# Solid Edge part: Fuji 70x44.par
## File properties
Title: Lines 70x44
Author: DESYS
Template: Parte SCARABEO.par
Last saved by: i.fialdini
Revision: 30
Application: Solid Edge
Tipo di contenuto documento: 0
Precisione: 0.990
Document Number: 6002
Revision: 0
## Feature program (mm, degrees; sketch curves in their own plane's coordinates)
sketch for "unnamed Protrusion 1" plane through (0, 0, 0) normal (0, -1, 0) x-axis (1, 0, 0)
  line (-245, 195) -> (-250, 190)
  line (-145, 195) -> (-245, 195)
  line (-145, 195) -> (-140, 190)
  dimension (linear) = 145
extrude "unnamed Protrusion 1" add finite 140 along -normal
fillet "Rotondo_22" radius 35
lofted cutout "unnamed LoftedCutout 1"
fillet "Rotondo_46" radius 90
sketch for "unnamed Cutout 1" plane through (0, 0, 0) normal (0, -1, 0) x-axis (-1, 0, 0)
  line (-265, -190) -> (265, -190)
  arc centre (265, -155) radius 35 from (300, -155) to (265, -190) cw
  line (300, -155) -> (300, 125)
  arc centre (265, 125) radius 35 from (265, 160) to (300, 125) cw
  line (265, 160) -> (-265, 160)
  arc centre (-265, 125) radius 35 from (-300, 125) to (-265, 160) cw
  line (-300, 125) -> (-300, -155)
  arc centre (-265, -155) radius 35 from (-300, -155) to (-265, -190) ccw
extrude "unnamed Cutout 1" cut along +normal
fillet "Rotondo_27" radius 10
sketch for "unnamed Protrusion 2" plane through (0, 25, 0) normal (0, -1, 0) x-axis (1, 0, 0)
extrude "unnamed Protrusion 2" add to key point along +normal
sketch for "Foro_9" plane through (0, 45, 0) normal (0, 1, 0) x-axis (0, 0, -1)
hole "Foro_9" diameter 50 through
sketch for "ProtrusioneEstrusa_8" plane through (0, 0, 0) normal (0, 0, 1) x-axis (1, 0, 0)
extrude "ProtrusioneEstrusa_8" add finite 50 symmetric
fillet "Rotondo_28" radius 10
fillet "Rotondo_29" radius 5
fillet "Rotondo_33" radius 15
fillet "Rotondo_34" radius 5
fillet "Rotondo_35" radius 5
sketch for "unnamed Cutout 2" plane through (0, 67.5, 215) normal (0, 0, 1) x-axis (1, 0, 0)
extrude "unnamed Cutout 2" cut through along -normal
fillet "Rotondo_38" radius 5
sketch for "unnamed Cutout 3" #1 plane through (0, 67.5, 215) normal (0, 0, 1) x-axis (1, 0, 0)
sketch for "unnamed Cutout 3" #2 plane through (0, 67.5, 215) normal (0, 0, 1) x-axis (1, 0, 0)
extrude "unnamed Cutout 3" cut through along -normal
sketch for "Foro_10" plane through (0, 67.5, 215) normal (0, 0, 1) x-axis (1, 0, 0)
  hole centre (-290, -37.5) bore radius 7.5
hole "Foro_10" finite
sketch for "unnamed Hole 1" plane through (0, 67.5, 215) normal (0, 0, 1) x-axis (1, 0, 0)
hole "unnamed Hole 1" finite
pattern "unnamed Pattern 1" of "Foro_10", "unnamed Hole 1"
fillet "Rotondo_39" radius 5
fillet "Rotondo_52" radius 10
fillet "Rotondo_53" radius 5
sketch for "unnamed Cutout 4" plane through (0, 0, 0) normal (0, -1, 0) x-axis (1, 0, 0)
extrude "unnamed Cutout 4" cut to key point along -normal
draft "Spoglia_3"  Angles1 = 5 deg
draft "Spoglia_4"  Angles1 = 5 deg
fillet "Rotondo_54" radius 5
mirror "unnamed Mirror 1" of "unnamed Cutout 4", "Spoglia_3", "Rotondo_54", "Spoglia_4" about plane through (0, 0, 0) normal (1, 0, 0)
extrude "unnamed Cutout 5" cut finite 105
draft "unnamed Draft 1"
draft "unnamed Draft 2"
fillet "unnamed Round 1"
Other named dimensions: "SuperficieOffset_2": Distance = 20 mm
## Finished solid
Body 1: sheet body, 4 faces, 12 edges, 10 vertices.
  Faces by surface: plane 2, blend 1, offset 1
  Edges by curve: circle 4, intersection 4, line 4
Body 2: solid body, 147 faces, 338 edges, 192 vertices.
  Faces by surface: cylinder 62, plane 35, torus 24, blend 20, sphere 4, offset 1, spline 1
  Edges by curve: circle 137, line 137, intersection 44, ellipse 20
Bounding box of the edges (mm; curved faces can reach further): 710.000 x 140.000 x 430.000, from (-355, 0, -215) to (355, 140, 215).
Cylindrical faces by radius (mm): R5 x36, R7.5 x2, R10 x4, R15 x6, R25 x3, R35 x10, R125.5769 x1
Toroidal faces (ring radius, tube radius in mm): R10 r5 x2, R20 r5 x2, R20 r15 x4, R30 r5 x13, R35 r10 x1, R40 r5 x1, R130.5769 r5 x1
Spherical faces by radius (mm): R5 x4
Planar faces by outward normal: +x 2, +y 4, +z 5, -x 2, -y 9, -z 7, oblique 6
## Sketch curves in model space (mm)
arc centre (0, 31.2658, -204.1392) radius 110 from (0, 45, -95) through (0, 108.0036, -125.3274) to (0, 140, -187.5)
arc centre (0, 31.2658, 204.1392) radius 110 from (0, 45, 95) through (0, 108.0036, 125.3274) to (0, 140, 187.5)
ellipse centre (0, 140, 0) radii 220, 187.5
arc centre (-255.5113, -36.4623, 0) radius 180 from (-95, 45, 0) through (-146.5964, 106.8469, 0) to (-220, 140, 0)
arc centre (255.5113, -36.4623, 0) radius 180 from (95, 45, 0) through (146.5964, 106.8469, 0) to (220, 140, 0)
circle centre (0, 45, 0) radius 95
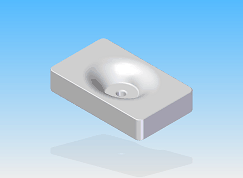
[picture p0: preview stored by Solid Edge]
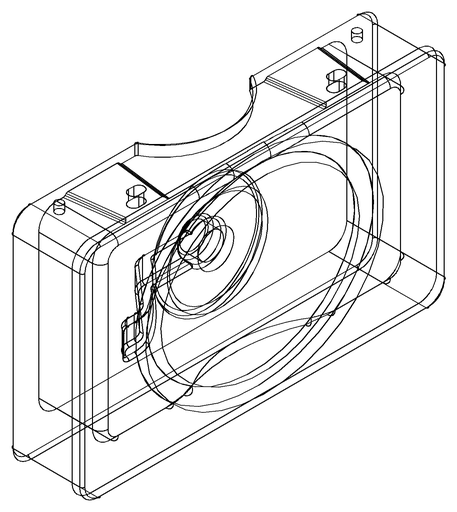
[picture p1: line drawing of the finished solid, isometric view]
